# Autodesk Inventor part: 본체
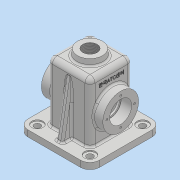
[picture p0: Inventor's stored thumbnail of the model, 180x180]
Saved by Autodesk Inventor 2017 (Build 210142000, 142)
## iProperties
Part Number: 본체
Material: 일반
Document SubType Name: Modeling
Designer: MRC
Density: 1 g/cm^3
Appearance: 기본값
Mass: 279.232 g
Surface Area: 865.472 cm^2
Volume: 279.232 cm^3
Author: MRC
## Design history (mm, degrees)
sketch "스케치1"
  geometry: L1 (-57, -57)-(57, -57); L2 (57, -57)-(57, 57); L3 (57, 57)-(-57, 57); L4 (-57, 57)-(-57, -57); L5 (-57, -57)-(57, 57); L6 (57, -57)-(-57, 57); 1 further point
  constraints: 12 end point, 2 midpoint, 2 parallel, 1 horizontal, 1 perpendicular
  dimensions: "d0" = 114 distance of L3.end L2.end; "d1" = 114 distance of L2.end L1.end
extrude "돌출1" new body sketch "스케치1" distance "d2" = 10; taper "d3" = 0 deg
sketch "스케치2"
  geometry: L1 (-34, -34)-(34, -34); L2 (34, -34)-(34, 34); L3 (34, 34)-(-34, 34); L4 (-34, 34)-(-34, -34); L5 (-34, -34)-(34, 34); L6 (34, -34)-(-34, 34); 1 further point
  constraints: 12 end point, 2 midpoint, 2 parallel, 1 horizontal, 1 perpendicular
  dimensions: "d4" = 68 distance of L3.end L2.end; "d5" = 68 distance of L2.end L1.end
extrude "돌출2" join sketch "스케치2" distance "d6" = 95; taper "d7" = 0 deg
feature "쉘1" dims "d10" = 10, "d11" = 5
sketch "스케치4"
  geometry: L1 (-10, 91)-(-10, -23) reference; C1 r 28.5 at (42, 34); 2 further points
  constraints: 1 centre point, 1 horizontal alignment, 1 midpoint
  dimensions: "d12" = 57 diameter of C1; "d13" = 52 distance from line of L1 C1.centre
extrude "돌출3" join sketch "스케치4" distance "d14" = 15; taper "d15" = 0 deg
hole "구멍1" diameter "d18" = 30; stored, may be unused: countersink angle "d22" = 90 deg, drill point angle "d24" = 118 deg; dims "d16" = 10, "d17" = 10, "d19" = 6, "d20" = 35, "d21" = 17, "d23" = 40
sketch "스케치5"
  geometry: C1 r 17.5 at (0, 0) reference; 2 further points
  constraints: 1 horizontal alignment
  dimensions: "d25" = 22 distance of C1.centre point (22, 0)
hole "구멍2" sketch "스케치5" at (22, 0) diameter "d26" = 3.242; stored, may be unused: countersink angle "d30" = 90 deg, drill point angle "d32" = 118 deg; dims "d27" = 8, "d28" = 35, "d29" = 17, "d31" = 10
node "작업 평면1"
sketch "스케치6"
  geometry: C1 r 20 at (0, 0); 1 further point
  constraints: 1 centre point, 1 coincident
  dimensions: "d37" = 40 diameter of C1
extrude "돌출4" join sketch "스케치6" stored distance "d38" = 10; taper "d39" = 8 deg
hole "구멍3" diameter "d42" = 22.835; stored, may be unused: countersink angle "d46" = 90 deg, drill point angle "d48" = 118 deg; dims "d40" = 10, "d41" = 10, "d43" = 40, "d44" = 35, "d45" = 17, "d47" = 40
sketch "스케치7"
  geometry: L1 (-34, 95.069)-(-49, 10); L2 (-57, 10)-(57, 10) reference; L3 (-34, 10)-(-34, 105) reference; L4 (-57, 0)-(-57, 10) reference; 1 further point
  constraints: 2 end point, 2 point on line
  dimensions: "d49" = 8 distance from line of L4 L1.end; "d50" = 10 deg angle of L4 L1
feature "리브1" sketch "스케치7" dims "d51" = 1, "d52" = 10, "d53" = 0, "d54" = 0, "d55" = 1, "d56" = 1
fillet "모깎기3" dims "d57" = 15
sketch "스케치8"
  geometry: A1 r 15 centre (42, 42) between (57, 42) and (42, 57) reference; A2 r 15 centre (-42, 42) between (-42, 57) and (-57, 42) reference; A3 r 15 centre (-42, -42) between (-57, -42) and (-42, -57) reference; A4 r 15 centre (42, -42) between (42, -57) and (57, -42) reference; 1 further point
hole "구멍4" sketch "스케치8" at (-42, 42), (-42, -42), (42, 42), (42, -42) diameter "d58" = 10; stored, may be unused: countersink angle "d62" = 90 deg, drill point angle "d64" = 118 deg; dims "d59" = 10, "d60" = 18, "d61" = 2, "d63" = 20
fillet "모깎기4" dims "d65" = 8
fillet "모깎기5" dims "d66" = 8
fillet "모깎기6" dims "d67" = 3
fillet "모깎기7" dims "d68" = 3
fillet "모깎기8" dims "d69" = 3
fillet "모깎기9" dims "d70" = 3
fillet "모깎기10" dims "d71" = 0.3
sketch "스케치9"
  geometry: L1 (0, -8)-(84, -8) reference; L2 (-18, 6)-(-18, 46) reference; 2 further points
  constraints: 1 other
  dimensions: "d72" = 34 distance from line of L1 point (7, 26); "d73" = 25 distance from line of point (7, 26) L2
feature "엠보싱1" sketch "스케치9" dims "d0" = 114, "d1" = 114, "d74" = 0.5, "d75" = 0
node "솔리드1"
pattern_circular "원형 패턴1" dims angle "d34" = 360 deg
mirror "미러1"
mirror "미러2"
